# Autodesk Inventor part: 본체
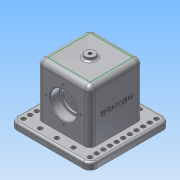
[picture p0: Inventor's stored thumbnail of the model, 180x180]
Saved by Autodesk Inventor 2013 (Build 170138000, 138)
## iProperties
Created: 2018-11
Part Number: 본체
Material: 알루미늄 6061
Document SubType Name: Modeling
Designer: Administrator
Density: 2.71 g/cm^3
Mass: 1022.46 g
Surface Area: 785.596 cm^2
Volume: 377.291 cm^3
Author: Administrator
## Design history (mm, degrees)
sketch "스케치2"
  geometry: L1 (-60, 60)-(60, 60); L2 (60, 60)-(60, -60); L3 (60, -60)-(-60, -60); L4 (-60, -60)-(-60, 60); 3 further points
  constraints: 8 end point, 2 midpoint, 2 parallel, 1 horizontal, 1 horizontal alignment, 1 perpendicular, 1 vertical alignment
  dimensions: "d0" = 120 distance of L1.start L1.end; "d2" = 120 distance of L1.end L2.end
extrude "돌출1" new body sketch "스케치2" distance "d3" = 10; taper "d4" = 0 deg
fillet "모깎기1" dims "d5" = 10
sketch "스케치5"
  geometry: L1 (-50, -60)-(50, -60) reference; L2 (60, -50)-(60, 50) reference; L3 (50, 60)-(-50, 60) reference; L4 (-60, 50)-(-60, -50) reference; L5 (-50, 50)-(-50, -50); L6 (-40, 50)-(-40, -50); L7 (-30, 50)-(-30, -50); L8 (-20, 50)-(-20, -50); L9 (-10, 50)-(-10, -50); L10 (0, 50)-(0, -50); L11 (10, 50)-(10, -50); L12 (20, 50)-(20, -50); L13 (30, 50)-(30, -50); L14 (40, 50)-(40, -50); L15 (-50, 50)-(50, 50); L16 (-50, 25)-(50, 25); L17 (-50, 0)-(50, 0); L18 (-50, -25)-(60, -25); L19 (-50, -50)-(50, -50); L20 (50, -50)-(50, 50); A1 r 10 centre (-50, 50) between (-50, 60) and (-60, 50) reference; A2 r 10 centre (-50, -50) between (-60, -50) and (-50, -60) reference; A3 r 10 centre (50, -50) between (50, -60) and (60, -50) reference; A4 r 10 centre (50, 50) between (60, 50) and (50, 60) reference; A5 r 10 centre (-50, 50) between (-50, 60) and (-60, 50) reference; 28 further points
  constraints: 32 end point, 26 coincident, 12 parallel, 5 point on line, 3 perpendicular, 2 midpoint
  dimensions: "d13" = 10 distance between parallel lines of L6 L5; "d15" = 10 distance between parallel lines of L7 L6; "d16" = 10 distance between parallel lines of L8 L7; "d17" = 10 distance between parallel lines of L8 L9; "d18" = 10 distance between parallel lines of L9 L10; "d19" = 10 distance between parallel lines of L11 L10; "d20" = 10 distance between parallel lines of L12 L11; "d21" = 10 distance between parallel lines of L13 L12; "d22" = 10 distance between parallel lines of L14 L13; "d23" = 25 distance between parallel lines of L16 L15; "d24" = 25 distance between parallel lines of L17 L16; "d25" = 25 distance between parallel lines of L18 L17
hole "구멍2" sketch "스케치5" diameter "d26" = 6.6; stored, may be unused: countersink angle "d30" = 90 deg, drill point angle "d32" = 0 deg; dims "d27" = 6, "d28" = 4, "d29" = 2, "d31" = 8
sketch "스케치6"
  geometry: L1 (-40, 40)-(40, 40); L2 (40, 40)-(40, -40); L3 (40, -40)-(-40, -40); L4 (-40, -40)-(-40, 40); 3 further points
  constraints: 8 end point, 2 midpoint, 2 parallel, 1 horizontal, 1 horizontal alignment, 1 perpendicular, 1 vertical alignment
  dimensions: "d33" = 80 distance of L1.start L1.end; "d35" = 80 distance of L3.end L1.start
extrude "돌출2" join sketch "스케치6" distance "d36" = 80; taper "d37" = 0 deg
fillet "모깎기2" dims "d38" = 8
fillet "모깎기3" dims "d39" = 8
sketch "스케치7"
  geometry: L1 (-23, 30)-(23, 30); L2 (23, 30)-(23, -30); L3 (23, -30)-(-23, -30); L4 (-23, -30)-(-23, 30); 3 further points
  constraints: 8 end point, 2 midpoint, 2 parallel, 1 horizontal, 1 horizontal alignment, 1 perpendicular, 1 vertical alignment
  dimensions: "d40" = 46 distance of L1.start L1.end; "d42" = 60 distance of L1.end L2.end
extrude "돌출3" cut sketch "스케치7" distance "d43" = 80; taper "d44" = 0 deg
fillet "모깎기4" dims "d45" = 3
sketch "스케치8"
  geometry: L1 (-67.73, 48)-(73.619, 48); L2 (-50, 0)-(50, 0) reference; L3 (-40, 10)-(-40, 82) reference; L4 (-40, 68)-(-26, 68); L5 (-26, 68)-(-26, 64.5); L6 (-26, 64.5)-(26, 64.5); L7 (26, 64.5)-(26, 68); L8 (26, 68)-(40, 68); L9 (40, 82)-(40, 10) reference; L10 (40, 48)-(-40, 48); L11 (-40, 68)-(-40, 48); L12 (40, 68)-(40, 48); L13 (-23, 77)-(-23, 0) reference; L14 (23, 0)-(23, 77) reference; 1 further point
  constraints: 18 end point, 6 point on line, 3 perpendicular, 2 collinear, 2 parallel, 1 horizontal
  dimensions: "d46" = 48 distance between parallel lines of L2 L1; "d47" = 16.5 distance between parallel lines of L10 L6; "d48" = 40 diameter of L4 L1; "d50" = 40 diameter of L8 L1; "d52" = 3 distance between parallel lines of L13 L5; "d53" = 3 distance between parallel lines of L14 L7
revolve "회전1" sketch "스케치8" stored, may be unused: angle "d51" = 90 deg
fillet "모깎기5" dims "d54" = 0.6
chamfer "모따기1" distance "d55" = 1; stored, may be unused: second distance "d56" = 2, angle "d57" = 45 deg
sketch "스케치12"
  geometry: L1 (-32, 32)-(32, 32) reference; L2 (-32, -32)-(-32, 32) reference; L3 (32, -32)-(-32, -32) reference; L4 (32, 32)-(32, -32) reference; 1 further point
sketch "스케치13"
  geometry: L1 (32, 32)-(32, -32) reference; L2 (0, 0)-(0, 52.14); L3 (0, 0)-(0, 0); C1 r 7.5 at (0, 0)
  constraints: 4 end point, 1 centre point, 1 coincident, 1 parallel, 1 perpendicular, 1 vertical alignment
  dimensions: "d58" = 15 diameter of C1
extrude "돌출4" join sketch "스케치13" distance "d60" = 5; taper "d61" = 0 deg
fillet "모깎기6" dims "d62" = 3
sketch "스케치14"
  geometry: C1 r 7.5 at (0, 0) reference; 1 further point
  constraints: 1 coincident
hole "구멍3" sketch "스케치14" at (0, 0) diameter "d63" = 4.917; stored, may be unused: countersink angle "d67" = 90 deg, drill point angle "d69" = 0 deg; dims "d64" = 18, "d65" = 4, "d66" = 2, "d68" = 20
sketch "스케치15" dims "d70" = 52
  geometry: L1 (72, 0)-(0, 0) reference; L2 (38, 32)-(38, 32); L3 (38, 32)-(38, 104.713); C1 r 21 at (38, 32) reference; 3 further points
  constraints: 4 end point, 2 vertical alignment, 1 coincident, 1 parallel, 1 perpendicular, 1 point on line, 2 other
hole "구멍4" sketch "스케치15" at (38, 58) diameter "d72" = 3.242; stored, may be unused: countersink angle "d76" = 90 deg, drill point angle "d78" = 118 deg; dims "d73" = 8, "d74" = 4, "d75" = 2, "d77" = 10
sketch "스케치16"
  geometry: L1 (82, -10)-(-18, -10) reference; 3 further points
  constraints: 1 midpoint, 1 vertical alignment, 1 other
  dimensions: "d82" = 48 distance from line of L1 point (32, 38)
extrude "돌출5" join sketch "스케치16" distance "d83" = 0.5; taper "d84" = 0 deg
fillet "모깎기7" dims "d85" = 3
sketch "스케치17"
  geometry: A1 r 7 centre (50, 50) between (57, 50) and (50, 57) reference; 1 further point
hole "구멍5" sketch "스케치17" at (50, 50) diameter "d86" = 6.6; stored, may be unused: countersink angle "d90" = 90 deg, drill point angle "d92" = 0 deg; dims "d87" = 8, "d88" = 4, "d89" = 2, "d91" = 10
node "솔리드1"
pattern_circular "원형 패턴1" dims angle "d80" = 360 deg
mirror "대칭1"
node "투영된 루프1"
